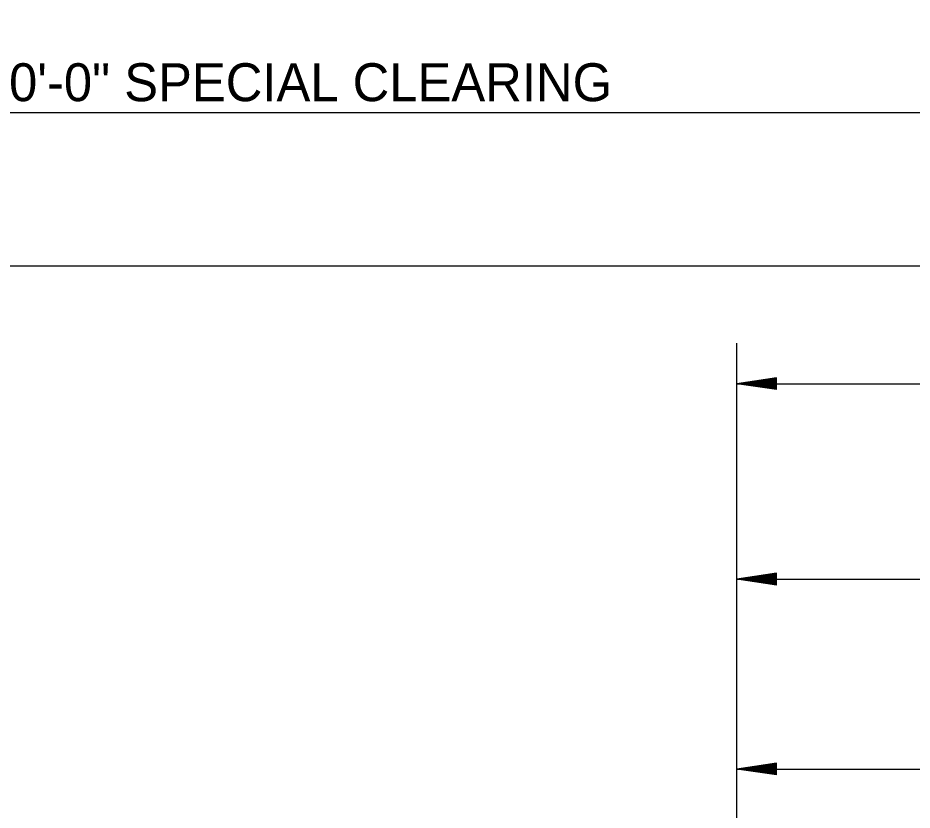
# Model space of a CAD drawing. Extents: x 1364961 to 1365294, y 367927 to 368034.
# Drawn here: x 1365016.31 to 1365029.89, y 367961.91 to 367973.93 of the extents above; entities that cross this region are included whole.
import ezdxf

# ---------------------------------------------------------------- set-up
doc = ezdxf.new("R2010")
doc.units = 0
doc.layers.add('Default', color=7, linetype='Continuous')

msp = doc.modelspace()

# ---------------------------------------------------------------- linework, layer by layer
at = {"layer": 'Default'}
for p, q in [((1365014.9, 367970.169), (1365077.207, 367970.169)), ((1365027.225, 367955.358), (1365027.225, 367968.995)), ((1365027.825, 367968.469), (1365027.225, 367968.379)), ((1365027.825, 367968.289), (1365027.225, 367968.379)), ((1365027.225, 367968.379), (1365065.197, 367968.379)), ((1365027.825, 367968.454), (1365027.325, 367968.379)), ((1365027.825, 367968.304), (1365027.325, 367968.379)), ((1365027.825, 367968.439), (1365027.428, 367968.379)), ((1365027.825, 367968.319), (1365027.428, 367968.379)), ((1365027.825, 367968.424), (1365027.528, 367968.379)), ((1365027.825, 367968.334), (1365027.528, 367968.379)), ((1365027.825, 367968.408), (1365027.63, 367968.379)), ((1365027.825, 367968.35), (1365027.63, 367968.379)), ((1365027.825, 367968.393), (1365027.73, 367968.379)), ((1365027.825, 367968.365), (1365027.73, 367968.379)), ((1365027.825, 367968.289), (1365027.825, 367968.469)), ((1365027.825, 367965.503), (1365027.225, 367965.413)), ((1365027.825, 367965.323), (1365027.225, 367965.413)), ((1365027.225, 367965.413), (1365065.197, 367965.413)), ((1365027.825, 367965.488), (1365027.325, 367965.413)), ((1365027.825, 367965.338), (1365027.325, 367965.413)), ((1365027.825, 367965.473), (1365027.428, 367965.413)), ((1365027.825, 367965.353), (1365027.428, 367965.413)), ((1365027.825, 367965.458), (1365027.528, 367965.413)), ((1365027.825, 367965.368), (1365027.528, 367965.413)), ((1365027.825, 367965.442), (1365027.63, 367965.413)), ((1365027.825, 367965.384), (1365027.63, 367965.413)), ((1365027.825, 367965.427), (1365027.73, 367965.413)), ((1365027.825, 367965.399), (1365027.73, 367965.413)), ((1365027.825, 367965.323), (1365027.825, 367965.503)), ((1365027.825, 367962.622), (1365027.225, 367962.532)), ((1365027.825, 367962.607), (1365027.325, 367962.532)), ((1365027.825, 367962.592), (1365027.428, 367962.532)), ((1365027.825, 367962.577), (1365027.528, 367962.532)), ((1365027.825, 367962.561), (1365027.63, 367962.532)), ((1365027.825, 367962.546), (1365027.73, 367962.532)), ((1365027.825, 367962.442), (1365027.825, 367962.622)), ((1365027.225, 367962.532), (1365065.197, 367962.532)), ((1365027.825, 367962.442), (1365027.225, 367962.532)), ((1365027.825, 367962.457), (1365027.325, 367962.532)), ((1365027.825, 367962.472), (1365027.428, 367962.532)), ((1365027.825, 367962.487), (1365027.528, 367962.532)), ((1365027.825, 367962.503), (1365027.63, 367962.532)), ((1365027.825, 367962.518), (1365027.73, 367962.532))]:
    msp.add_line(p, q, dxfattribs=at)
msp.add_lwpolyline([(1365031.225, 367972.489), (1365011.325, 367972.489), (1365010.468, 367973.929), (1365010.04, 367970.573), (1365009.611, 367972.489), (1365001.225, 367972.489)], dxfattribs=at)

# ---------------------------------------------------------------- texts
msp.add_text('30\'-0" SPECIAL CLEARING', height=0.576, dxfattribs=at).set_placement((1365015.749, 367972.665))

doc.saveas('drawing.dxf')
